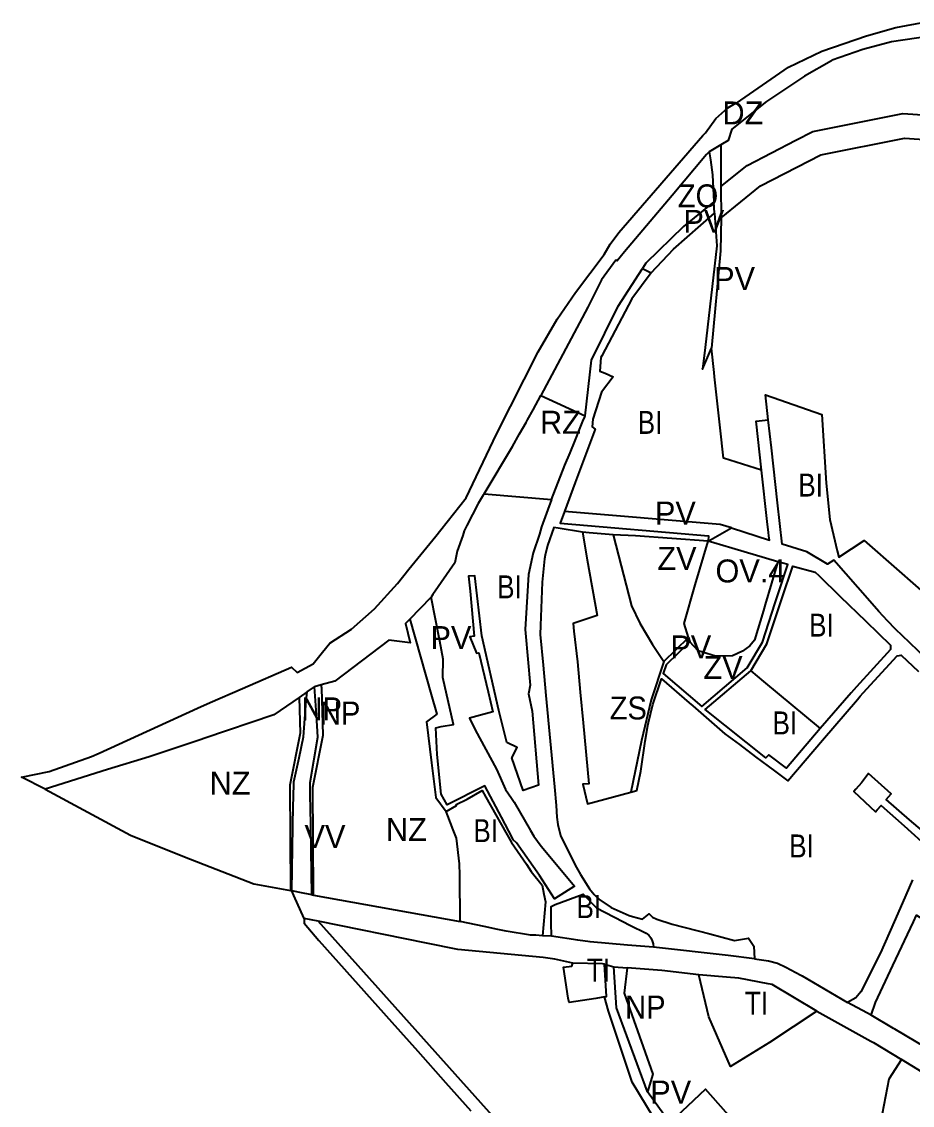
# Model space of a CAD drawing. Extents: x -650451 to -642268, y -1075216 to -1066610.
# Drawn here: x -650451 to -649869, y -1070006 to -1069298 of the extents above; entities that cross this region are included whole.
import ezdxf

# ---------------------------------------------------------------- set-up
doc = ezdxf.new("R2010")
doc.units = 0
doc.header["$LTSCALE"] = 6
doc.layers.add('1', color=7, linetype='Continuous', lineweight=35)
doc.layers.add('2', color=7, linetype='Continuous')
doc.layers.add('3', color=7, linetype='Continuous')

msp = doc.modelspace()

# ---------------------------------------------------------------- linework, layer by layer
at = {"layer": '1'}
for p, q in [((-649994.38, -1069378.33), (-650002.11, -1069382.8)), ((-649994.329, -1069405.451), (-649994.293, -1069425.949)), ((-649998.512, -1069422.926), (-649999.01, -1069415.628)), ((-650045.72, -1069459.1), (-650040.012, -1069461.999)), ((-650112.18, -1069542.11), (-650083.1, -1069555.34)), ((-650149.19, -1069606.26), (-650105.19, -1069610.01)), ((-650002.65, -1069637.14), (-649987.49, -1069628.6)), ((-650197.7, -1069688.08), (-650183.82, -1069673.87)), ((-650031.64, -1069715.9), (-650015.53, -1069700.21)), ((-650015.53, -1069700.21), (-650014.74, -1069702.9)), ((-650264.91, -1069735.69), (-650270.059, -1069739.232)), ((-650264.91, -1069735.69), (-650259.97, -1069732.29)), ((-650255.716, -1069731.162), (-650259.97, -1069732.29)), ((-650275.76, -1069865.474), (-650274.95, -1069865.62)), ((-650261.8, -1069868.33), (-650260.645, -1069868.536)), ((-650260.645, -1069868.536), (-650164.75, -1069885.61)), ((-650257.713, -1069885.547), (-650266.89, -1069883.7)), ((-650105.1, -1069895.27), (-650110.99, -1069894.94)), ((-650070.55, -1069913.65), (-650064.44, -1069915.23)), ((-650064.44, -1069915.23), (-650055.55, -1069915.97))]:
    msp.add_line(p, q, dxfattribs=at)
for points in [[(-650436.18, -1069799.13), (-650451.45, -1069791.42), (-650433.41, -1069787.66), (-650405.89, -1069777.8), (-650400.78, -1069775.64), (-650336.4, -1069746.4), (-650328.24, -1069742.69), (-650307.16, -1069733.49), (-650275.1, -1069719.48), (-650271.36, -1069723.01), (-650260.85, -1069717.27), (-650254.87, -1069709.76), (-650250.08, -1069703.74), (-650235.79, -1069694.79), (-650220.75, -1069681.49), (-650205.82, -1069664.8), (-650198.33, -1069655.56), (-650180.79, -1069633.89), (-650177.51, -1069629.84), (-650160.99, -1069608.81), (-650141.06, -1069567.33), (-650113.74, -1069513.61), (-650101.42, -1069492.09), (-650089.39, -1069474.82), (-650070.7, -1069449.98), (-650066.79, -1069443.23), (-650060.99, -1069435.54), (-650006.14, -1069372.3), (-650004.39, -1069370.35), (-649997.61, -1069361.2), (-649989.83, -1069354.13), (-649984.29, -1069350.79), (-649984.09, -1069351.02), (-649950.25, -1069327.47), (-649928.34, -1069317.14), (-649899.28, -1069306.99), (-649880.08, -1069301.68), (-649860.14, -1069297.84)], [(-649509.42, -1069372.61), (-649517.17, -1069374.3), (-649537.32, -1069375.23), (-649582.25, -1069374.51), (-649607.18, -1069370.92), (-649627.76, -1069366.8), (-649645.03, -1069358.8), (-649670.23, -1069347.9), (-649688.73, -1069338.7), (-649690.59, -1069337.98), (-649741.5, -1069317.74), (-649785.8, -1069308.94), (-649789, -1069308.31), (-649813.3, -1069303.66), (-649848.62, -1069305.95), (-649882.93, -1069311.1), (-649901.58, -1069316.01), (-649921.54, -1069323.03), (-649922.11, -1069323.35), (-649939.81, -1069333.47), (-649964.53, -1069350.02), (-649987.12, -1069368.03), (-649989.67, -1069375.36), (-649994.38, -1069378.33)], [(-649994.329, -1069405.451), (-649977.239, -1069391.714), (-649945.397, -1069375.277), (-649934.363, -1069369.537), (-649875.434, -1069357.751), (-649810.846, -1069362.154), (-649755.971, -1069381.179), (-649688.625, -1069418.156), (-649582.972, -1069502.334)], [(-649994.293, -1069425.949), (-649968.465, -1069405.189), (-649929.015, -1069384.784), (-649874.391, -1069373.859), (-649814.067, -1069377.972), (-649762.488, -1069395.854), (-649697.525, -1069431.522), (-649598.004, -1069510.814)], [(-650002.11, -1069382.8), (-650003.73, -1069384.71), (-650026.33, -1069411.47), (-650057.49, -1069448.18), (-650060.29, -1069451.7), (-650062.17, -1069454.05), (-650063.12, -1069453.54), (-650072.5, -1069466.44), (-650081.29, -1069484.35), (-650112.18, -1069542.11)], [(-650002.11, -1069382.8), (-650001.13, -1069388.13), (-649999.95, -1069397.98), (-649999.01, -1069415.628)], [(-649994.38, -1069378.33), (-649994.35, -1069394.43), (-649994.34, -1069398.8), (-649994.329, -1069405.451)], [(-649999.01, -1069415.628), (-650018.873, -1069431.749), (-650043.521, -1069455.69), (-650045.72, -1069459.1)], [(-650040.012, -1069461.999), (-650025.31, -1069446.49), (-649998.512, -1069422.926)], [(-649998.512, -1069422.926), (-649997.06, -1069444.22), (-650004.57, -1069510.77), (-650006.33, -1069524.77), (-650000.59, -1069511.15)], [(-649994.293, -1069425.949), (-649994.53, -1069447.61), (-650000.59, -1069511.15)], [(-650083.1, -1069555.34), (-650079, -1069518.93), (-650061.51, -1069483.79), (-650045.72, -1069459.1)], [(-650040.012, -1069461.999), (-650052.68, -1069478.83), (-650072.18, -1069516.15), (-650072.79, -1069517.3), (-650073.42, -1069526.19), (-650069.92, -1069527.41), (-650064.71, -1069529.78), (-650072.51, -1069539.93), (-650078.05, -1069557.42), (-650078.46, -1069562.62), (-650076.5, -1069564.13), (-650089.55, -1069598.9), (-650096.627, -1069617.746)], [(-649967.81, -1069590.74), (-649992.589, -1069582.88), (-649994.794, -1069563.119), (-649998.5, -1069529.88), (-649998.81, -1069527.07), (-650000.59, -1069511.15)], [(-650149.19, -1069606.26), (-650130.57, -1069575.27), (-650125.94, -1069567.19), (-650121.59, -1069559.59), (-650120.7, -1069558.03), (-650117.19, -1069551.46), (-650112.18, -1069542.11)], [(-649963.43, -1069557.91), (-649965.26, -1069541.51), (-649928.48, -1069554.57), (-649925.53, -1069599.38), (-649923.17, -1069623.14), (-649918.35, -1069643.45), (-649917.38, -1069647.56), (-649900.64, -1069636.78), (-649877.82, -1069656.83), (-649859.96, -1069672.53), (-649859.17, -1069673.22), (-649857.49, -1069671.46), (-649833.941, -1069695.24)], [(-650105.19, -1069610.01), (-650096.36, -1069587.63), (-650093, -1069579.43), (-650089.68, -1069571.36), (-650086.32, -1069563.16), (-650084.69, -1069558.83), (-650083.34, -1069555.91), (-650083.1, -1069555.34)], [(-649967.81, -1069590.74), (-649971.38, -1069558.79), (-649963.43, -1069557.91)], [(-649833.941, -1069695.24), (-649840.59, -1069702.06), (-649855.95, -1069717.81), (-649865.16, -1069709.14), (-649871.1, -1069703.42), (-649880.23, -1069694.74), (-649885.41, -1069689.3), (-649891.19, -1069683.08), (-649896.97, -1069676.43), (-649920.45, -1069649.53), (-649924.8, -1069652.19), (-649938.2, -1069644.23), (-649954.38, -1069639.099), (-649957.37, -1069612.18), (-649961.38, -1069576.24), (-649963.43, -1069557.91)], [(-649987.49, -1069628.6), (-649962.71, -1069636.458), (-649963.011, -1069633.76), (-649963.26, -1069631.49), (-649964.066, -1069624.3), (-649967.81, -1069590.74)], [(-650149.19, -1069606.26), (-650149.77, -1069607.22), (-650152.96, -1069612.53), (-650160.4, -1069626.97), (-650162.1, -1069630.49), (-650163.17, -1069633.49), (-650166.82, -1069643.66), (-650168.4, -1069651.27), (-650182.78, -1069672.09), (-650183.82, -1069673.87)], [(-650105.19, -1069610.01), (-650111.69, -1069627.86), (-650113.01, -1069632.68), (-650117.18, -1069644.8), (-650120.2, -1069659.04), (-650122.26, -1069694.82), (-650122.13, -1069697.33), (-650119.1, -1069731.21), (-650120.13, -1069737), (-650117.65, -1069748.28), (-650113.5, -1069796.6), (-650123.63, -1069800.11), (-650131.1, -1069778.76), (-650127.52, -1069772.07), (-650134.41, -1069768.77), (-650138.51, -1069752.27), (-650139.6, -1069747.91), (-650150.72, -1069699.05), (-650155.3, -1069659.94), (-650159.3, -1069660.17), (-650158.38, -1069669.92), (-650155.62, -1069699.22), (-650158.59, -1069699.65), (-650154.18, -1069710.42), (-650152.7, -1069710.16), (-650146.53, -1069735.65), (-650143.37, -1069748.68), (-650153.86, -1069751.49), (-650158.74, -1069752.8), (-650155.1, -1069760.48), (-650140.99, -1069786.24), (-650135.25, -1069799.36), (-650131.27, -1069805.04), (-650129.55, -1069807.68), (-650118.92, -1069826.21), (-650116.74, -1069830.03), (-650111.83, -1069836.4), (-650108.28, -1069840.67), (-650090.16, -1069862.54), (-650103.19, -1069870.95), (-650112.97, -1069855.55), (-650128.08, -1069834.19), (-650130.15, -1069832.23), (-650130.61, -1069831.34), (-650137.86, -1069817.54), (-650148.59, -1069797.1), (-650173.21, -1069809.54), (-650177.29, -1069802.53), (-650179.85, -1069776.68), (-650180.81, -1069759.05), (-650177.18, -1069758.38), (-650169.26, -1069756.93), (-650176.23, -1069726.19), (-650175.82, -1069714.32), (-650178.16, -1069702.51), (-650183.82, -1069673.87)], [(-650096.627, -1069617.746), (-650099.55, -1069625.53), (-650002.39, -1069633.65), (-650002.65, -1069637.14)], [(-649987.49, -1069628.6), (-649994.913, -1069626.246), (-650096.627, -1069617.746)], [(-650084.9, -1069631.28), (-650100.78, -1069628.81), (-650103.56, -1069628.38), (-650107.67, -1069639.98), (-650109.21, -1069646.43), (-650109.79, -1069648.83), (-650111.14, -1069664), (-650112.22, -1069692.23), (-650112.45, -1069698.2), (-650110.6, -1069718.12), (-650108.74, -1069738.03), (-650103.19, -1069797.78), (-650102.06, -1069809.88), (-650101.56, -1069817.62), (-650100.93, -1069822.28), (-650099.33, -1069829.47), (-650089.66, -1069848.89), (-650086.22, -1069855.06), (-650080.2, -1069864.37), (-650077.16, -1069867.93), (-650073.45, -1069871.54), (-650066.01, -1069876.48), (-650054.28, -1069881.73), (-650052.24, -1069882.31), (-650045.59, -1069884.22), (-650041.22, -1069880.58), (-650039.19, -1069882.79), (-650036.21, -1069884.06), (-650026.14, -1069887.34), (-650001.7, -1069893.71), (-649985.42, -1069898.02), (-649976.42, -1069896.61), (-649972.83, -1069901.83), (-649972.35, -1069910.04)], [(-650084.9, -1069631.28), (-650081.73, -1069649.38), (-650075.35, -1069685.77), (-650089.57, -1069690.53), (-650090.98, -1069691), (-650090.41, -1069696.07), (-650088.19, -1069716.03), (-650086.34, -1069735.95), (-650084.48, -1069755.86), (-650080.78, -1069795.7), (-650084.63, -1069796.06), (-650081.66, -1069808.87), (-650053.2, -1069801.11)], [(-650064.77, -1069633.06), (-650080.52, -1069631.67), (-650084.9, -1069631.28)], [(-650002.65, -1069637.14), (-650050.26, -1069633.65), (-650064.77, -1069633.06)], [(-650064.77, -1069633.06), (-650052.88, -1069679.49), (-650047.45, -1069690.69), (-650039.11, -1069704.76), (-650031.64, -1069715.9)], [(-650015.53, -1069700.21), (-650018.31, -1069690.89), (-650011.15, -1069665.82), (-650002.65, -1069637.14)], [(-649957.15, -1069650.76), (-649987.32, -1069641.73), (-649999.03, -1069638.22), (-650002.65, -1069637.14)], [(-650014.74, -1069702.9), (-650030.26, -1069717.96), (-650032.13, -1069723.75), (-650006.85, -1069745.3), (-649977.31, -1069720.05), (-649967.27, -1069703.29), (-649958.87, -1069677.59), (-649957.54, -1069673.5), (-649950.69, -1069652.54), (-649957.15, -1069650.76)], [(-649957.15, -1069650.76), (-649965.45, -1069678.6), (-649966.59, -1069682.44), (-649972.35, -1069701.78), (-649975.45, -1069705.65), (-649980.22, -1069709.07), (-649986.69, -1069712.03), (-649998, -1069712.26), (-650009.29, -1069708.92), (-650014.74, -1069702.9)], [(-649974.86, -1069721.96), (-649964.3, -1069704.18), (-649954.47, -1069674.82), (-649947.32, -1069653.47), (-649932.7, -1069657.49), (-649930.41, -1069659.71), (-649916.38, -1069673.34), (-649899.74, -1069689.5), (-649883.6, -1069705.18), (-649883.49, -1069708.04), (-649905.82, -1069732.28), (-649909.27, -1069736.29), (-649929.38, -1069759.65)], [(-650197.7, -1069688.08), (-650200.5, -1069690.94), (-650197.58, -1069703.52), (-650211.41, -1069701.88), (-650246.69, -1069728.77), (-650255.716, -1069731.162)], [(-650197.7, -1069688.08), (-650183.73, -1069737.28), (-650180.04, -1069750.27), (-650186.91, -1069755.15), (-650183.51, -1069781.92), (-650180.63, -1069804.63), (-650173.87, -1069813.75)], [(-650053.2, -1069801.11), (-650049.34, -1069800.06), (-650046.82, -1069787.47), (-650043.81, -1069767.85), (-650042.24, -1069757.54), (-650041.79, -1069755.67), (-650038.92, -1069743.89), (-650033.2, -1069727.08), (-650015.15, -1069742.74), (-650012.77, -1069744.8), (-649991.78, -1069763.02), (-649982.24, -1069770.15), (-649971.65, -1069778.08), (-649959.43, -1069787.24), (-649950.7, -1069793.76), (-649927.86, -1069767.23), (-649905.05, -1069740.69), (-649903.24, -1069738.49), (-649901.42, -1069736.29), (-649879.07, -1069712.16), (-649876.61, -1069711.74), (-649865.19, -1069722.43)], [(-650031.64, -1069715.9), (-650040.01, -1069740.9), (-650046.28, -1069767.47), (-650053.2, -1069801.11)], [(-649929.38, -1069759.65), (-649951.56, -1069785.42), (-649963, -1069776.7), (-649965, -1069778.7), (-650004.59, -1069747.27), (-649974.86, -1069721.96)], [(-649974.86, -1069721.96), (-649966.52, -1069728.87), (-649929.38, -1069759.65)], [(-650274.95, -1069865.62), (-650273.87, -1069809.74), (-650273.78, -1069805.2), (-650273.58, -1069794.48), (-650270.15, -1069778.65), (-650267.22, -1069765.1), (-650265.37, -1069741.61), (-650264.91, -1069735.69)], [(-650261.8, -1069868.33), (-650262.7, -1069809.89), (-650262.77, -1069805.54), (-650262.93, -1069794.84), (-650257.77, -1069765.2), (-650258.74, -1069750.62), (-650259.97, -1069732.29)], [(-650260.645, -1069868.536), (-650260.748, -1069867.327), (-650261.204, -1069797.969), (-650254.411, -1069764.006), (-650255.21, -1069733.253), (-650255.716, -1069731.162)], [(-650270.059, -1069739.232), (-650286.67, -1069750.66), (-650331.8, -1069765.87), (-650334.85, -1069766.9), (-650368.01, -1069778.07), (-650395.34, -1069786.29), (-650436.18, -1069799.13)], [(-650270.059, -1069739.232), (-650269.449, -1069762.714), (-650276.214, -1069796.532), (-650275.76, -1069865.474)], [(-649855.38, -1069832.63), (-649871.2, -1069819.33), (-649886.3, -1069805.96), (-649883.11, -1069802.36), (-649897.98, -1069788.95), (-649902.52, -1069795), (-649906.21, -1069799.28), (-649907.42, -1069800.68), (-649893.39, -1069814.03), (-649892.16, -1069812.65), (-649889.7, -1069809.88), (-649874.62, -1069823.28), (-649858.72, -1069837.54)], [(-650436.18, -1069799.13), (-650380.32, -1069829.19), (-650344.93, -1069843.43), (-650299.78, -1069861.15), (-650275.76, -1069865.474)], [(-650173.87, -1069813.75), (-650167.1, -1069809.79), (-650167.33, -1069809.33), (-650160.23, -1069805.73), (-650160.21, -1069805.77), (-650150.51, -1069800.1), (-650148.09, -1069804.36), (-650131.29, -1069833.99), (-650121.5, -1069848.27), (-650118.34, -1069852.9), (-650111.13, -1069861.88), (-650110.01, -1069867.87), (-650109.09, -1069872.83), (-650110.99, -1069894.94)], [(-650164.75, -1069885.61), (-650165.06, -1069855.42), (-650165.14, -1069847.93), (-650167.17, -1069831.25), (-650169.29, -1069825.71), (-650172.79, -1069816.55), (-650173.87, -1069813.75)], [(-649869.14, -1069858.43), (-649875.76, -1069873.46), (-649881.22, -1069885.84), (-649890.13, -1069906.05), (-649902.95, -1069931.63), (-649906.24, -1069935.53), (-649911.72, -1069938.49)], [(-650266.89, -1069883.7), (-650273.61, -1069868.62), (-650274.95, -1069865.62)], [(-650261.8, -1069868.33), (-650269.59, -1069866.73), (-650272.69, -1069866.09), (-650274.95, -1069865.62)], [(-650105.1, -1069895.27), (-650105.28, -1069886.55), (-650105.32, -1069875.9), (-650102.77, -1069874.52), (-650084.41, -1069867.81), (-650075.69, -1069876.78), (-650058.37, -1069885.69), (-650053.97, -1069887.96), (-650043.33, -1069893.26), (-650041.52, -1069894.6), (-650040.22, -1069896.33), (-650039.25, -1069898.23), (-650038.62, -1069900.29), (-650038.38, -1069902.54)], [(-650266.89, -1069883.7), (-650266.68, -1069886.78), (-650257.16, -1069898.07), (-650209.51, -1069951.43), (-650192.51, -1069970.47), (-650174.3, -1069990.86), (-650157.87, -1070009.26)], [(-650091.19, -1069912.91), (-650102.82, -1069910.23), (-650110.46, -1069909.09), (-650166.37, -1069903.94), (-650186.81, -1069899.82), (-650257.713, -1069885.547)], [(-649843.513, -1070347.685), (-650257.713, -1069885.547)], [(-650110.99, -1069894.94), (-650115.4, -1069894.63), (-650118.87, -1069894.67), (-650134.75, -1069891.93), (-650140.09, -1069890.81), (-650149.02, -1069888.93), (-650164.75, -1069885.61)], [(-649896.09, -1069946.92), (-649893.38, -1069938.59), (-649882.04, -1069914.43), (-649868.5, -1069885.82), (-649866.41, -1069881.57), (-649849.67, -1069891.96), (-649837.77, -1069899.34), (-649828.29, -1069905.24), (-649819.85, -1069910.47), (-649802.84, -1069921.03), (-649791.59, -1069928.01), (-649811.3, -1069958.77), (-649829.04, -1069986.55)], [(-650038.38, -1069902.54), (-650055.46, -1069901.08), (-650079.86, -1069899), (-650087.94, -1069897.81), (-650105.1, -1069895.27)], [(-649972.35, -1069910.04), (-649989.53, -1069907.89), (-650038.38, -1069902.54)], [(-650070.36, -1069934.96), (-650072.66, -1069935.33), (-650076.17, -1069935.89), (-650093.66, -1069938.66), (-650094.12, -1069935.66), (-650097.23, -1069915.55), (-650091.77, -1069914.85), (-650091.19, -1069912.91)], [(-650070.55, -1069913.65), (-650071.71, -1069913.35), (-650091.19, -1069912.91)], [(-650070.36, -1069934.96), (-650069.07, -1069934.76), (-650070.55, -1069913.65)], [(-649972.35, -1069910.04), (-649963.24, -1069911.36), (-649957.41, -1069912.87), (-649951.88, -1069915.4), (-649942.06, -1069920.72), (-649941.3, -1069921.13), (-649911.72, -1069938.49)], [(-650042.39, -1069996.88), (-650062.72, -1069942.14), (-650064.44, -1069915.23)], [(-650055.55, -1069915.97), (-650057.67, -1069932.49), (-650038.92, -1069985.32), (-650042.39, -1069996.88)], [(-650008.9, -1069920.42), (-650033.04, -1069917.65), (-650055.55, -1069915.97)], [(-649931.76, -1069944.31), (-649962.67, -1069964.78), (-649988.08, -1069980.36), (-650002.19, -1069947.99), (-650008.9, -1069920.42)], [(-649931.76, -1069944.31), (-649960.93, -1069926.88), (-649963.58, -1069926.38), (-649982.64, -1069922.74), (-649990.72, -1069922.02), (-650008.9, -1069920.42)], [(-650033.55, -1070021.52), (-650052.48, -1069990.73), (-650067.94, -1069944.24), (-650070.36, -1069934.96)], [(-649896.09, -1069946.92), (-649898.92, -1069945.38), (-649911.72, -1069938.49)], [(-649931.76, -1069944.31), (-649896.43, -1069963.81), (-649894.68, -1069964.78), (-649876.31, -1069975.93)], [(-649829.04, -1069986.55), (-649836.9, -1069981.9), (-649841.71, -1069979.06), (-649846.1, -1069976.46), (-649866.77, -1069964.25), (-649880.59, -1069956.08), (-649881.61, -1069955.48), (-649896.09, -1069946.92)], [(-649876.31, -1069975.93), (-649884.59, -1069988.57), (-649891.21, -1070022.68)], [(-649784.87, -1070116.76), (-649791.31, -1070051.51), (-649797.45, -1070023.77), (-649853.14, -1069989.98), (-649876.31, -1069975.93)], [(-650033.55, -1070021.52), (-650038.78, -1070026.24), (-650072.57, -1070056.71), (-650068.42, -1070061.31), (-650065.43, -1070064.63), (-650053.4, -1070077.97), (-650027.58, -1070106.62), (-650013.97, -1070121.71), (-650010.44, -1070125.63), (-649963.86, -1070083.92), (-649942.76, -1070065.03), (-649964.64, -1070040.29), (-650004.5, -1069995.2), (-650027.71, -1070017.13), (-650042.39, -1069996.88)]]:
    msp.add_lwpolyline(points, dxfattribs=at)

# ---------------------------------------------------------------- texts
at = {"layer": '2'}
for s, p in [('DZ', (-649993.36, -1069364.918)), ('PV', (-649998.808, -1069473.125)), ('RZ', (-650112.606, -1069567.024)), ('OV.4', (-649997.92, -1069664.17)), ('PV', (-650184.213, -1069707.719)), ('PV', (-650027.43, -1069713.802)), ('NZ', (-650328.597, -1069802.811)), ('NZ', (-650213.331, -1069833.105)), ('VV', (-650266.546, -1069837.693)), ('PV', (-650040.539, -1070004.608))]:
    msp.add_text(s, height=15, dxfattribs=at).set_placement(p)
for s, width, p in [('BI', 0.85, (-650048.761, -1069567.12)), ('BI', 0.85, (-649943.747, -1069608.052)), ('BI', 0.85, (-650140.625, -1069674.542)), ('BI', 0.85, (-649936.709, -1069699.545)), ('ZS', 0.95, (-650067.11, -1069753.69)), ('BI', 0.85, (-650156.183, -1069833.822)), ('BI', 0.85, (-649949.715, -1069843.827)), ('BI', 0.85, (-650088.766, -1069883.459)), ('TI', 0.85, (-650082, -1069924.9)), ('NP', 0.95, (-650057.013, -1069949.043)), ('TI', 0.85, (-649978.73, -1069946.61))]:
    msp.add_text(s, height=15, dxfattribs=dict(at, width=width)).set_placement(p)
at = {"layer": '3'}
for s, width, p in [('ZO', 0.95, (-650022.551, -1069419.118)), ('NP', 0.95, (-650268.536, -1069754.301)), ('NP', 0.95, (-650256.49, -1069756.989)), ('BI', 0.85, (-649960.613, -1069763.456))]:
    msp.add_text(s, height=15, dxfattribs=dict(at, width=width)).set_placement(p)
for s, p in [('PV', (-650018.873, -1069435.772)), ('PV', (-650037.502, -1069626.328)), ('ZV', (-650035.894, -1069655.953)), ('ZV', (-650005.78, -1069727.207))]:
    msp.add_text(s, height=15, dxfattribs=at).set_placement(p)

doc.saveas('drawing.dxf')
